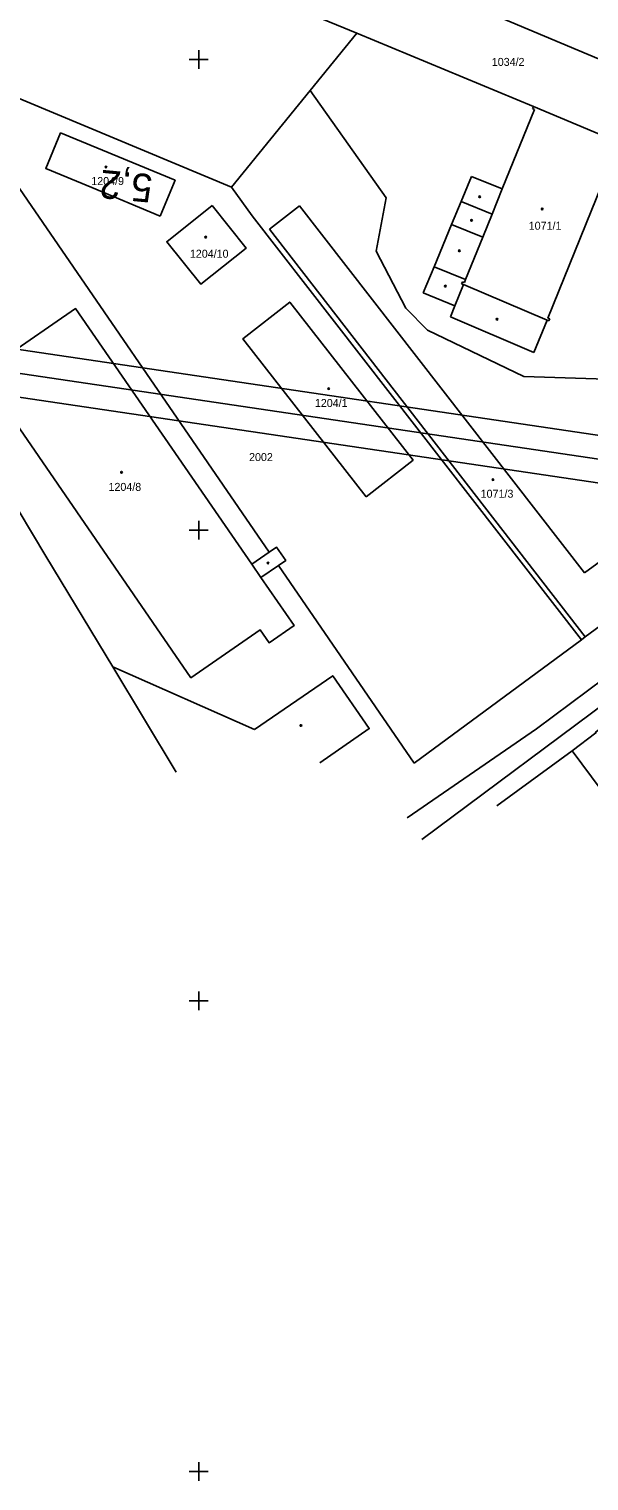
# Model space of a CAD drawing. Extents: x -779302 to -774398, y -1144902 to -1142831.
# Drawn here: x -775436.1 to -775317, y -1144802 to -1144493.5 of the extents above; entities that cross this region are included whole.
import ezdxf

# ---------------------------------------------------------------- set-up
doc = ezdxf.new("R2010")
doc.units = 0
for name, color, linetype in [('hektosit - Vrstva 5', 7, 'Continuous'), ('Hranice parcel', 7, 'Continuous'), ('Parcelní čísla', 7, 'Continuous'), ('Vnitřní kresba', 7, 'Continuous'), ('Vrstva 1', 7, 'Continuous'), ('zjednodus_g_situ-seda - Vrstva 7', 7, 'Continuous'), ('Značky budov', 7, 'Continuous')]:
    doc.layers.add(name, color=color, linetype=linetype)

msp = doc.modelspace()

# ---------------------------------------------------------------- linework, layer by layer
at = {"layer": 'hektosit - Vrstva 5'}
for p, q in [((-775402, -1144500), (-775398, -1144500)), ((-775400, -1144498), (-775400, -1144502)), ((-775400, -1144598), (-775400, -1144602)), ((-775402, -1144600), (-775398, -1144600)), ((-775400, -1144698), (-775400, -1144702)), ((-775402, -1144700), (-775398, -1144700)), ((-775400, -1144798), (-775400, -1144802)), ((-775402, -1144800), (-775398, -1144800))]:
    msp.add_line(p, q, dxfattribs=at)
at = {"layer": 'Hranice parcel'}
for p, q in [((-775435.74, -1144465.74), (-775366.41, -1144494.44)), ((-775253.51, -1144525.7), (-775380, -1144472.53)), ((-775366.41, -1144494.44), (-775376.32, -1144506.59)), ((-775393.05, -1144527.1), (-775456.54, -1144500.61)), ((-775456.54, -1144500.61), (-775385.01, -1144604.68)), ((-775376.32, -1144506.59), (-775393.05, -1144527.1)), ((-775383.06, -1144607.52), (-775354.18, -1144649.53)), ((-775318.59, -1144623.31), (-775354.18, -1144649.53)), ((-775418.26, -1144629.06), (-775388.11, -1144642.34)), ((-775404.79, -1144651.38), (-775418.26, -1144629.06)), ((-775320.64, -1144646.86), (-775336.62, -1144658.59)), ((-775320.64, -1144646.86), (-775308.02, -1144663.87))]:
    msp.add_line(p, q, dxfattribs=at)
for points in [[(-775261.18, -1144541.39), (-775270.96, -1144536.68), (-775294.22, -1144525.5), (-775310.26, -1144517.79), (-775328.85, -1144510.01), (-775366.41, -1144494.44)], [(-775376.32, -1144506.59), (-775360.11, -1144529.4), (-775362.24, -1144540.72), (-775355.95, -1144552.84), (-775351.38, -1144557.51), (-775330.85, -1144567.36), (-775284.69, -1144568.85), (-775263.45, -1144562.01), (-775246.07, -1144570.05)], [(-775408.19, -1144533.28), (-775405.01, -1144525.66), (-775429.35, -1144515.62), (-775432.5, -1144523.14), (-775422.69, -1144527.23), (-775408.19, -1144533.28)], [(-775393.05, -1144527.1), (-775388.65, -1144533.19), (-775318.59, -1144623.31)], [(-775397.1, -1144531.04), (-775406.77, -1144538.71), (-775399.54, -1144547.76), (-775389.9, -1144540.08), (-775397.1, -1144531.04)], [(-775418.26, -1144629.06), (-775432.46, -1144605.51), (-775467.43, -1144547.15)], [(-775385.01, -1144604.68), (-775388.73, -1144607.24), (-775426.16, -1144552.94), (-775441.55, -1144563.53), (-775442.48, -1144562.18), (-775445.69, -1144564.39), (-775444.76, -1144565.75), (-775446.18, -1144566.73), (-775401.66, -1144631.36), (-775386.91, -1144621.19), (-775385.03, -1144623.93), (-775379.73, -1144620.28), (-775386.77, -1144610.08), (-775383.06, -1144607.52)], [(-775364.41, -1144592.92), (-775354.44, -1144585.1), (-775380.64, -1144551.55), (-775390.61, -1144559.33), (-775364.41, -1144592.92)], [(-775318.59, -1144623.31), (-775317.85, -1144622.66), (-775257.86, -1144578.79), (-775246.07, -1144570.05)], [(-775383.06, -1144607.52), (-775381.5, -1144606.44), (-775383.46, -1144603.61), (-775385.01, -1144604.68)], [(-775374.28, -1144649.4), (-775363.74, -1144642.14), (-775371.51, -1144630.92), (-775388.11, -1144642.34)], [(-775307.84, -1144637.35), (-775311.74, -1144640.25), (-775311.83, -1144640.13), (-775315.63, -1144642.95), (-775315.54, -1144643.07), (-775320.64, -1144646.86)]]:
    msp.add_lwpolyline(points, dxfattribs=at)
at = {"layer": 'Vnitřní kresba'}
for p, q in [((-775329.02, -1144510.43), (-775328.85, -1144510.01)), ((-775335.46, -1144527.5), (-775328.6, -1144510.6)), ((-775328.6, -1144510.6), (-775329.02, -1144510.43)), ((-775310.85, -1144518.04), (-775325.78, -1144554.96)), ((-775342.03, -1144524.84), (-775344.23, -1144530.17)), ((-775335.46, -1144527.5), (-775342.03, -1144524.84)), ((-775337.63, -1144532.84), (-775335.46, -1144527.5)), ((-775378.54, -1144531.1), (-775384.93, -1144536.07)), ((-775317.98, -1144609.04), (-775378.54, -1144531.1)), ((-775344.23, -1144530.17), (-775346.26, -1144535.06)), ((-775344.23, -1144530.17), (-775337.63, -1144532.84)), ((-775339.62, -1144537.76), (-775337.63, -1144532.84)), ((-775384.93, -1144536.07), (-775317.85, -1144622.66)), ((-775346.26, -1144535.06), (-775349.97, -1144544.03)), ((-775346.26, -1144535.06), (-775339.62, -1144537.76)), ((-775343.26, -1144546.75), (-775339.62, -1144537.76)), ((-775349.97, -1144544.03), (-775352.28, -1144549.61)), ((-775349.97, -1144544.03), (-775343.26, -1144546.75)), ((-775343.52, -1144547.4), (-775343.26, -1144546.75)), ((-775352.28, -1144549.61), (-775345.53, -1144552.35)), ((-775345.53, -1144552.35), (-775343.69, -1144547.82)), ((-775344.11, -1144547.65), (-775343.94, -1144547.23)), ((-775343.69, -1144547.82), (-775344.11, -1144547.65)), ((-775343.94, -1144547.23), (-775343.52, -1144547.4)), ((-775343.69, -1144547.82), (-775325.95, -1144555.38)), ((-775346.48, -1144554.7), (-775345.53, -1144552.35)), ((-775328.74, -1144562.28), (-775346.48, -1144554.7)), ((-775325.95, -1144555.38), (-775328.74, -1144562.28)), ((-775325.53, -1144555.54), (-775325.95, -1144555.38)), ((-775325.78, -1144554.96), (-775325.36, -1144555.13)), ((-775325.36, -1144555.13), (-775325.53, -1144555.54)), ((-775219.39, -1144566.53), (-775352.58, -1144665.72)), ((-775264.3, -1144570.05), (-775317.98, -1144609.04)), ((-775269.86, -1144598.82), (-775328.21, -1144642.2)), ((-775388.73, -1144607.24), (-775386.77, -1144610.08)), ((-775355.7, -1144661.12), (-775328.21, -1144642.2))]:
    msp.add_line(p, q, dxfattribs=at)
at = {"layer": 'Vrstva 1'}
for points in [[(-774799.29, -1144366.04), (-776045.7, -1144181.56), (-776089.18, -1144475.34), (-774842.77, -1144659.83)], [(-774846.98, -1144654.15), (-776083.5, -1144471.13), (-776041.48, -1144187.23), (-774804.97, -1144370.25)], [(-774810.64, -1144374.46), (-775834.48, -1144222.92), (-775875.04, -1144496.94), (-774851.19, -1144648.48)], [(-774851.19, -1144648.48), (-775875.04, -1144496.94), (-775834.48, -1144222.92), (-774810.64, -1144374.46)]]:
    msp.add_lwpolyline(points, close=True, dxfattribs=at)
at = {"layer": 'Značky budov'}
for centre in [(-775419.7, -1144522.85), (-775340.26, -1144529.17), (-775326.98, -1144531.77), (-775342, -1144534.18), (-775398.53, -1144537.75), (-775344.59, -1144540.64), (-775347.58, -1144548.15), (-775336.6, -1144555.18), (-775372.35, -1144569.93), (-775416.4, -1144587.71), (-775337.43, -1144589.27), (-775385.27, -1144606.99), (-775378.27, -1144641.5)]:
    msp.add_circle(centre, 0.175, dxfattribs=at)

# ---------------------------------------------------------------- texts
at = {"layer": 'Parcelní čísla'}
for s, p in [('1034/2', (-775337.69, -1144501.37)), ('1204/9', (-775422.83, -1144526.68)), ('1071/1', (-775329.84, -1144536.17)), ('1204/10', (-775401.87, -1144542.12)), ('1204/1', (-775375.3, -1144573.83)), ('2002', (-775389.29, -1144585.32)), ('1204/8', (-775419.17, -1144591.66)), ('1071/3', (-775340.06, -1144593.11))]:
    msp.add_text(s, height=1.7, dxfattribs=at).set_placement(p)
at = {"layer": 'zjednodus_g_situ-seda - Vrstva 7'}
msp.add_text('5,2', height=6, rotation=174.6024, dxfattribs=at).set_placement((-775409.6, -1144524.47))

doc.saveas('drawing.dxf')
